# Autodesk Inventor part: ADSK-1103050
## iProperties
Shininess: 41.0
Length Units: 11272
Angle Units: 11279
Time Units: 11290
Mass Units: 11286
Length Display Precision: 4
Angle Display Precision: 2
Compacted: True
Created: 2000-08
Part Number: ADSK-1103050
Document SubType Name: Modeling
Mass: 0.0484654 g
Surface Area: 3.07418 cm^2
Volume: 0.0484654 cm^3
Density: 1 g/cm^3
Density: 0.0
Volumn: 0.0
Area: 0.0
PropertySet Name: Model Information
Control State: 0
Master: False
Checked Out: False
